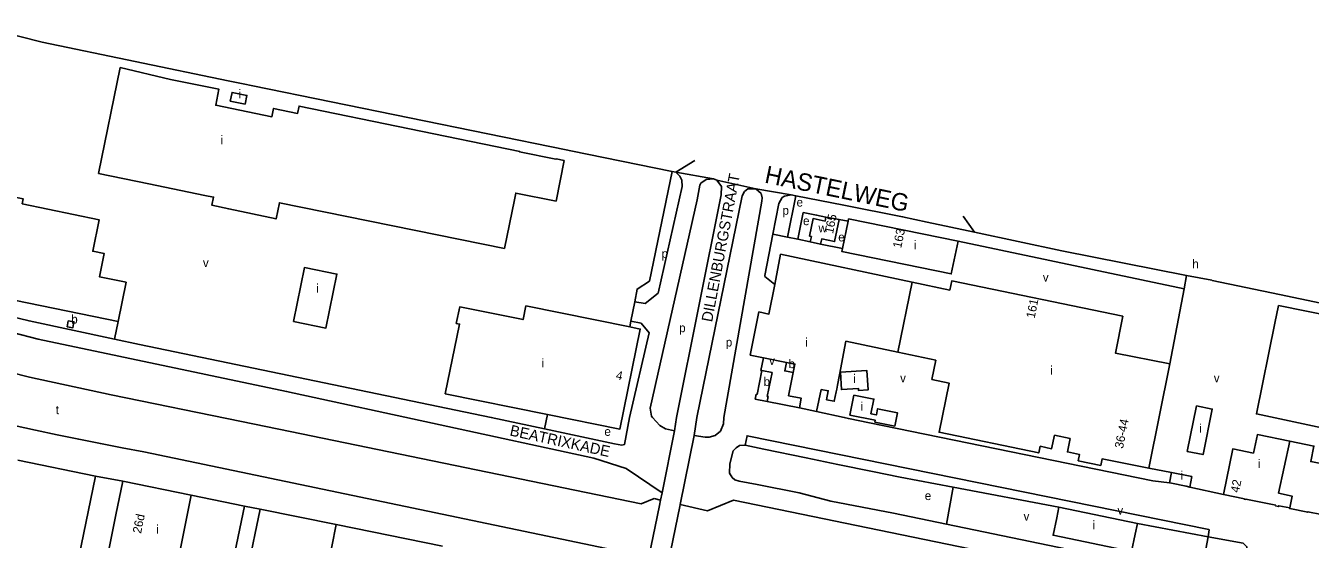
# Model space of a CAD drawing. Extents: x 157699 to 159683, y 381451 to 383293.
# Drawn here: x 158379 to 158969, y 382844 to 383080 of the extents above; entities that cross this region are included whole.
import ezdxf

# ---------------------------------------------------------------- set-up
doc = ezdxf.new("R2010")
doc.units = 0
for name, color, linetype in [('BLT_Basislijn', 7, 'Continuous'), ('BLT_Bebouwing', 7, 'Continuous'), ('BLT_Centroide', 7, 'Continuous'), ('BLT_Huisnummer', 7, 'Continuous'), ('BLT_Huisnummer_reeks', 7, 'Continuous'), ('BLT_Onderverdeling_panden', 7, 'Continuous'), ('BLT_Straatnaam', 7, 'Continuous'), ('BLT_Straatnaam_hoofdweg', 7, 'Continuous'), ('BLT_Vlakafsluiter', 7, 'Continuous')]:
    doc.layers.add(name, color=color, linetype=linetype)

msp = doc.modelspace()

# ---------------------------------------------------------------- linework, layer by layer
at = {"layer": 'BLT_Basislijn'}
for p, q in [((158471.46, 383054.68), (158478.43, 383053.24)), ((158478.43, 383053.24), (158482.8, 383052.33)), ((158482.8, 383052.33), (158626.84, 383022.89)), ((158732.3, 383001.78), (158754.29, 382997.48)), ((158735.71, 382994.09), (158733.22, 382981.8)), ((158756.28, 382990.14), (158752.12, 382990.83)), ((158792.59, 382989.62), (158814.28, 382985.14)), ((158728.41, 382982.78), (158721.7, 382984.14)), ((158738.9, 382980.65), (158733.22, 382981.8)), ((158743.66, 382979.62), (158753.73, 382977.65)), ((158806.76, 382980.92), (158910.57, 382959.04)), ((158910.57, 382959.04), (158911.74, 382965.21)), ((158904.02, 382924.52), (158910.57, 382959.04)), ((158923.52, 382962.9), (158954.36, 382956.52)), ((158421.02, 382944.05), (158419.39, 382935.87)), ((158656.55, 382944.26), (158655.97, 382941.52)), ((158719.06, 382907.21), (158733.94, 382904.31)), ((158618.18, 382901.35), (158616.78, 382894.79)), ((158676.58, 382893.8), (158670.83, 382865.28)), ((158896.32, 382870.89), (158772.13, 382896.23)), ((158685.61, 382891.63), (158679.11, 382859.91)), ((158645.35, 382839.82), (158432.83, 382884.22)), ((158736.95, 382881.41), (158717.61, 382885.4)), ((158374.91, 382880.36), (158410.62, 382872.97)), ((158751.62, 382878.38), (158736.95, 382881.41)), ((158767.45, 382875.07), (158751.62, 382878.38)), ((158894.43, 382876.58), (158904.84, 382874.67)), ((158384.61, 382747.34), (158410.62, 382872.97)), ((158410.62, 382872.97), (158423.18, 382870.75)), ((158706.21, 382870.73), (158714.47, 382869.08)), ((158780.17, 382872.45), (158804.57, 382867.85)), ((158903.87, 382869.87), (158896.32, 382870.89)), ((158670.16, 382861.98), (158670.83, 382865.28)), ((158733.8, 382865.3), (158748.34, 382861.49)), ((158804.57, 382867.85), (158853.12, 382858.7)), ((158928.69, 382864.6), (158913.17, 382867.98)), ((158479.05, 382859.19), (158486.16, 382857.78)), ((158664.82, 382835.75), (158669.66, 382859.56)), ((158667.13, 382862.68), (158670.16, 382861.98)), ((158669.66, 382859.56), (158670.16, 382861.98)), ((158678.92, 382859.01), (158673.76, 382833.82)), ((158679.11, 382859.91), (158678.92, 382859.01)), ((158679.11, 382859.91), (158691.76, 382856.98)), ((158486.16, 382857.78), (158461.09, 382737.28)), ((158486.16, 382857.78), (158521.2, 382850.79)), ((158801.5, 382851), (158777.17, 382856.05)), ((158918.11, 382826.83), (158801.5, 382851)), ((158889.18, 382851.26), (158921.71, 382845.17)), ((158918.11, 382826.83), (158921.71, 382845.17))]:
    msp.add_line(p, q, dxfattribs=at)
for points in [[(158356.41, 383079.95), (158386.16, 383072.35), (158471.46, 383054.68)], [(158626.84, 383022.89), (158628.87, 383022.48), (158675.51, 383012.99)], [(158658.25, 382953.07), (158659.39, 382958.95), (158665.11, 382962.64), (158675.51, 383012.99)], [(158677.11, 383012.68), (158679.06, 383010.76), (158679.92, 383008.9), (158680, 383006.07), (158669.03, 382957.1), (158663.04, 382952.34), (158658.25, 382953.07)], [(158675.51, 383012.99), (158677.11, 383012.68)], [(158676.58, 382893.8), (158672.33, 382894.68), (158669.78, 382896.27), (158666.4, 382900), (158665.93, 382900.61), (158665.35, 382904.23), (158686.92, 382999.9), (158688.15, 383006.6), (158688.67, 383007.57), (158691.07, 383009.33), (158694.42, 383009.61)], [(158696.02, 383008.9), (158698.1, 383006.13), (158697.94, 383002.2), (158677.44, 382900), (158676.58, 382893.8)], [(158694.42, 383009.61), (158696.02, 383008.9)], [(158713.84, 383005.01), (158716.3, 383002.78), (158716.75, 383000.83), (158716.59, 382999.3), (158699.21, 382900), (158699.06, 382897), (158697.62, 382893.72), (158695.17, 382891.65), (158692.53, 382890.86), (158690.65, 382890.86), (158685.61, 382891.63)], [(158685.61, 382891.63), (158686.87, 382900), (158707.61, 383001.72), (158708.64, 383003.74), (158710.23, 383005.01), (158713.84, 383005.01)], [(158730.2, 383002.22), (158727.07, 383001.63), (158725.95, 383000.96), (158724.48, 382998.29), (158721.7, 382984.14)], [(158728.41, 382982.78), (158732.3, 383001.78)], [(158732.3, 383001.78), (158730.2, 383002.22)], [(158746.12, 382992.05), (158741.8, 382992.92), (158735.71, 382994.09)], [(158754.29, 382997.48), (158781.31, 382992.19), (158792.59, 382989.62)], [(158235.21, 382984.68), (158245.72, 382980.3), (158271.82, 382971.51), (158290.28, 382964.15), (158310.07, 382957.16), (158337.03, 382948.25), (158384.31, 382935.92), (158498.38, 382911.93), (158639.44, 382881.31), (158654.28, 382876.43), (158670.83, 382865.28)], [(158721.7, 382984.14), (158718, 382965.24), (158718, 382964.77), (158722.56, 382961.08)], [(158733.22, 382981.8), (158728.41, 382982.78)], [(158814.28, 382985.14), (158854.43, 382976.43)], [(158854.43, 382976.43), (158911.74, 382965.21)], [(158911.74, 382965.21), (158923.27, 382962.96), (158923.52, 382962.9)], [(158419.39, 382935.87), (158380.08, 382944.33), (158355.97, 382950.23), (158342.01, 382954.28)], [(158656.55, 382944.26), (158658.25, 382953.07)], [(158954.36, 382956.52), (158973.38, 382952.52), (158974.67, 382952.26)], [(158649.03, 382887.89), (158652.28, 382887.23), (158653.52, 382887.47), (158655.92, 382900), (158664.92, 382938.86), (158661.22, 382943.27), (158656.55, 382944.26)], [(158430.81, 382933.41), (158419.39, 382935.87)], [(158616.78, 382894.79), (158592.39, 382900), (158430.81, 382933.41)], [(158342.79, 382927.93), (158380.32, 382918.52), (158417.72, 382910.35), (158477.61, 382898.06), (158500, 382893.46)], [(158716.7, 382921.48), (158716.21, 382921.58), (158717.37, 382927.4)], [(158432.83, 382884.22), (158422.84, 382886.04), (158412.88, 382887.94), (158402.92, 382889.92), (158392.99, 382891.97), (158383.07, 382894.1), (158373.17, 382896.31), (158363.28, 382898.6), (158353.41, 382900.97), (158344.05, 382903.29)], [(158741.81, 382902.63), (158754.49, 382900), (158756.43, 382899.44), (158766.17, 382897.48), (158772.13, 382896.23)], [(158649.03, 382887.89), (158616.78, 382894.79)], [(158500, 382893.46), (158661.25, 382860.33), (158667.13, 382862.68)], [(158709.02, 382887.28), (158709.88, 382891.54), (158921.96, 382848.54), (158922.18, 382848.38), (158921.71, 382845.17)], [(158709.02, 382887.28), (158706.38, 382887.1), (158704.87, 382885.97), (158703.51, 382884.65), (158701.9, 382878.59), (158701.8, 382874.33), (158702.97, 382872.42), (158704.24, 382871.23), (158706.21, 382870.73)], [(158717.61, 382885.4), (158709.02, 382887.28)], [(158767.45, 382875.07), (158780.17, 382872.45)], [(158733.8, 382865.3), (158714.47, 382869.08)], [(158804.57, 382867.85), (158801.5, 382851)], [(158691.76, 382856.98), (158703.62, 382861.92), (158796.54, 382842.79), (158889.46, 382823.66)], [(158777.17, 382856.05), (158748.34, 382861.49)], [(158936.46, 382823.03), (158939.58, 382838.18), (158939.46, 382840.58), (158937.71, 382842.17), (158921.71, 382845.17)]]:
    msp.add_lwpolyline(points, dxfattribs=at)
at = {"layer": 'BLT_Bebouwing'}
for p, q in [((158411.97, 383011.97), (158421.94, 383060.76)), ((158752.12, 382990.83), (158746.12, 382992.05)), ((158756.49, 382991.18), (158806.76, 382980.92)), ((158738.9, 382980.65), (158743.66, 382979.62)), ((158785.73, 382962.1), (158725.3, 382974.93)), ((158424.69, 382962.1), (158421.02, 382944.05)), ((158803.03, 382958.43), (158785.73, 382962.1)), ((158752.3, 382919.56), (158755.29, 382935.02)), ((158755.29, 382935.02), (158779.09, 382929.98)), ((158779.09, 382929.98), (158796.55, 382926.28)), ((158715.93, 382927.69), (158717.37, 382927.4)), ((158717.37, 382927.4), (158727.94, 382925.26)), ((158796.55, 382926.28), (158794.7, 382917.35)), ((158728.95, 382909.85), (158731.07, 382920.54)), ((158751.38, 382914.78), (158752.3, 382919.56)), ((158743.95, 382912.83), (158741.81, 382902.63)), ((158750.79, 382911.74), (158751.04, 382913.01)), ((158751.04, 382913.01), (158751.38, 382914.78)), ((158719.06, 382907.21), (158713.6, 382908.32)), ((158861.92, 382879.95), (158872.35, 382877.86)), ((158423.18, 382870.75), (158454.49, 382864.27)), ((158454.49, 382864.27), (158479.05, 382859.19)), ((158928.69, 382864.6), (158938.32, 382862.64)), ((158479.05, 382859.19), (158459.06, 382762.75)), ((158510.92, 382800.12), (158521.2, 382850.79)), ((158521.2, 382850.79), (158570.05, 382840.89)), ((158889.18, 382851.26), (158888.17, 382846.36))]:
    msp.add_line(p, q, dxfattribs=at)
for points in [[(158421.94, 383060.76), (158445.02, 383055.29), (158467.32, 383050.72), (158465.82, 383043.38), (158491.61, 383038.08), (158492.4, 383041.95), (158503.45, 383039.62), (158504.12, 383043), (158605.45, 383022.16), (158605.41, 383021.97), (158622.09, 383018.56), (158622.13, 383018.73), (158625.93, 383017.95)], [(158479.3, 383043.94), (158480.11, 383047.9), (158473.33, 383049.28), (158472.51, 383045.31), (158479.3, 383043.94)], [(158622.12, 382999.29), (158625.93, 383017.95)], [(158435.14, 383007.24), (158411.97, 383011.97)], [(158460.78, 383002), (158435.14, 383007.24)], [(158369.45, 382999.63), (158369.92, 383001.9), (158377.43, 383000.36), (158376.97, 382998.11), (158412.27, 382990.82), (158409.3, 382976.31), (158414.6, 382975.23), (158412.42, 382964.59), (158424.69, 382962.1)], [(158598.42, 382977.61), (158495.1, 382998.61), (158493.54, 382991.2), (158471.79, 382995.79), (158464.05, 382997.44), (158464.82, 383001.17), (158460.78, 383002)], [(158598.42, 382977.61), (158603.01, 383000), (158603.63, 383003.07), (158622.12, 382999.29)], [(158746.12, 382992.05), (158745.74, 382990.17), (158740.21, 382991.29), (158738.59, 382983.25), (158739.39, 382983.09), (158738.9, 382980.65)], [(158743.66, 382979.62), (158744.14, 382981.98), (158750.08, 382980.77), (158752.12, 382990.83)], [(158753.73, 382977.65), (158756.28, 382990.14)], [(158756.28, 382990.14), (158756.49, 382991.18)], [(158806.76, 382980.92), (158803.69, 382965.92), (158753.43, 382976.2), (158753.73, 382977.65)], [(158725.3, 382974.93), (158722.56, 382961.08)], [(158501.51, 382944.05), (158516.41, 382941), (158521.47, 382965.79), (158506.57, 382968.83), (158501.51, 382944.05)], [(158421.02, 382944.05), (158326.92, 382963.3)], [(158722.56, 382961.08), (158719.94, 382947.47), (158715.32, 382948.41), (158711.31, 382928.63), (158715.93, 382927.69)], [(158803.03, 382958.43), (158803.9, 382962.69), (158882.49, 382946.53)], [(158608.25, 382951.24), (158606.99, 382944.95), (158577.87, 382950.76), (158576.3, 382943.16), (158577.81, 382942.84), (158571.28, 382910.82), (158618.18, 382901.35)], [(158655.97, 382941.52), (158608.25, 382951.24)], [(158954.01, 382951.45), (158952.34, 382943.32)], [(158994.08, 382943.25), (158954.01, 382951.45)], [(158618.18, 382901.35), (158651.46, 382894.62), (158660.83, 382940.53), (158655.97, 382941.52)], [(158882.49, 382946.53), (158879.08, 382929.51), (158904.02, 382924.52)], [(158952.34, 382943.32), (158943.81, 382901.6), (158976.07, 382894.73), (158978.21, 382905.21), (158985.97, 382903.62), (158991.98, 382932.99)], [(158727.94, 382925.26), (158727.15, 382921.34), (158731.07, 382920.54)], [(158904.02, 382924.52), (158894.43, 382876.58)], [(158713.6, 382908.32), (158714.07, 382910.65), (158714.49, 382910.57), (158716.7, 382921.48)], [(158716.7, 382921.48), (158721.34, 382920.54), (158719.13, 382909.63), (158719.53, 382909.55), (158719.06, 382907.21)], [(158851.03, 382891.74), (158849.76, 382885.61), (158844.52, 382886.7), (158843.88, 382883.65), (158798.07, 382893.15), (158802.74, 382915.68), (158794.7, 382917.35)], [(158750.79, 382911.74), (158749.95, 382907.4), (158746.39, 382908.12), (158747.18, 382912.21), (158743.95, 382912.83)], [(158728.95, 382909.85), (158734.79, 382908.74), (158733.94, 382904.31)], [(158733.94, 382904.31), (158741.81, 382902.63)], [(158851.03, 382891.74), (158858.25, 382890.21)], [(158858.25, 382890.21), (158857, 382884.13), (158862.5, 382882.98), (158861.92, 382879.95)], [(158959.1, 382889.1), (158944.27, 382892.12), (158942.54, 382883.58)], [(158977.95, 382877.81), (158968.79, 382879.68), (158970.26, 382886.82), (158959.1, 382889.1)], [(158942.54, 382883.58), (158932.95, 382885.53), (158928.69, 382864.6)], [(158894.43, 382876.58), (158872.95, 382880.9), (158872.35, 382877.86)], [(158423.18, 382870.75), (158419.98, 382855.29), (158416.52, 382838.4)], [(158903.87, 382869.87), (158904.84, 382874.67)], [(158904.84, 382874.67), (158914.14, 382872.78), (158913.17, 382867.98)], [(158904.78, 382869.69), (158903.87, 382869.87)], [(158913.17, 382867.98), (158911.5, 382868.32), (158904.78, 382869.69)], [(158888.17, 382846.36), (158886.52, 382838.4), (158850.46, 382845.84), (158852.1, 382853.78), (158853.12, 382858.7)], [(158853.12, 382858.7), (158889.18, 382851.26)], [(158938.32, 382862.64), (158938.27, 382862.41), (158938.93, 382862.28), (158938.96, 382862.42), (158952.71, 382859.63)], [(158952.71, 382859.63), (158952.64, 382859.3), (158953.99, 382859.02), (158954.07, 382859.42), (158959.21, 382858.38)], [(158959.21, 382858.38), (158959.15, 382858.05), (158967.39, 382856.38), (158967.44, 382856.62), (158973.64, 382855.36)]]:
    msp.add_lwpolyline(points, dxfattribs=at)
for points in [[(158398.09, 382944.37), (158400.68, 382943.91), (158400.21, 382941.2), (158397.62, 382941.65)], [(158752.72, 382920.74), (158753.21, 382912.78), (158760.98, 382913.26), (158761.03, 382912.36), (158765.46, 382912.63), (158764.91, 382921.49)], [(158758.97, 382910.27), (158757.1, 382901.06), (158768.77, 382898.69), (158768.59, 382897.84), (158777.69, 382896), (158778.92, 382902.08), (158769.83, 382903.93), (158769.26, 382901.11), (158766.75, 382901.62), (158768.13, 382908.41)], [(158916.27, 382905.25), (158912.09, 382884.37), (158919.34, 382882.92), (158923.52, 382903.8)]]:
    msp.add_lwpolyline(points, close=True, dxfattribs=at)
at = {"layer": 'BLT_Onderverdeling_panden'}
for p, q in [((158785.73, 382962.1), (158779.09, 382929.98)), ((158959.1, 382889.1), (158953.93, 382865.15)), ((158454.49, 382864.27), (158447.07, 382827.2))]:
    msp.add_line(p, q, dxfattribs=at)
for points in [[(158727.94, 382925.26), (158731.86, 382924.46), (158731.07, 382920.54)], [(158953.93, 382865.15), (158960.31, 382863.74), (158959.21, 382858.38)]]:
    msp.add_lwpolyline(points, dxfattribs=at)
at = {"layer": 'BLT_Vlakafsluiter'}
for p, q in [((158685.9, 383018), (158677.11, 383012.68)), ((158694.42, 383009.61), (158677.11, 383012.68)), ((158713.84, 383005.01), (158696.02, 383008.9)), ((158730.2, 383002.22), (158713.84, 383005.01)), ((158809.11, 382992.44), (158814.28, 382985.14))]:
    msp.add_line(p, q, dxfattribs=at)

# ---------------------------------------------------------------- texts
at = {"layer": 'BLT_Centroide'}
for s, p in [('i', (158476.31, 383046.62)), ('i', (158468.07, 383025.5)), ('e', (158732.6, 382996.83)), ('p', (158726.12, 382993.1)), ('e', (158735.57, 382988.3)), ('w', (158742.68, 382984.94)), ('e', (158751.74, 382980.85)), ('p', (158670.58, 382973.22)), ('i', (158786.44, 382977.26)), ('v', (158459.94, 382969.09)), ('h', (158914.38, 382968.51)), ('v', (158845.72, 382962.38)), ('i', (158511.98, 382957.31)), ('b', (158399.46, 382943.11)), ('p', (158678.68, 382939.13)), ('p', (158700.09, 382932.54)), ('i', (158736.61, 382932.5)), ('i', (158615.49, 382922.94)), ('v', (158719.99, 382924.11)), ('b', (158728.91, 382922.62)), ('i', (158849.11, 382919.62)), ('b', (158717.47, 382914.42)), ('i', (158758.66, 382915.81)), ('v', (158780.16, 382916.13)), ('v', (158924.24, 382916.13)), ('i', (158762.03, 382903.03)), ('t', (158392.32, 382901.46)), ('e', (158644.34, 382891.5)), ('i', (158917.5, 382892.96)), ('i', (158944.5, 382876.69)), ('i', (158909, 382871.31)), ('e', (158791.48, 382862)), ('v', (158879.96, 382855.34)), ('v', (158836.88, 382852.57)), ('i', (158868.49, 382848.56)), ('i', (158438.52, 382846.58))]:
    msp.add_text(s, height=4, dxfattribs=at).set_placement(p)
at = {"layer": 'BLT_Huisnummer'}
for s, rotation, p in [('165', 78.53784, (158749.34, 382984.17)), ('163', 78.44054, (158780.66, 382977.51)), ('4', 348.32759, (158649.38, 382917.59)), ('42', 78.60696, (158935.79, 382865.16)), ('26d', 78.31386, (158431.5, 382846.42))]:
    msp.add_text(s, height=4, rotation=rotation, dxfattribs=at).set_placement(p)
at = {"layer": 'BLT_Huisnummer_reeks'}
for s, p in [('161', (158841.94, 382945.27)), ('36-44', (158882.53, 382885.42))]:
    msp.add_text(s, height=4, rotation=78.67812, dxfattribs=at).set_placement(p)
at = {"layer": 'BLT_Straatnaam'}
for s, rotation, p in [('DILLENBURGSTRAAT', 79.31023, (158693.8, 382943.54)), ('BEATRIXKADE', 347.68993, (158600.59, 382891.73))]:
    msp.add_text(s, height=5, rotation=rotation, dxfattribs=at).set_placement(p)
at = {"layer": 'BLT_Straatnaam_hoofdweg'}
msp.add_text('HASTELWEG', height=8, rotation=348.32481, dxfattribs=at).set_placement((158717.53, 383007.89))

doc.saveas('drawing.dxf')
